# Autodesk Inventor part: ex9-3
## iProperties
Author: Administrator
Created: 2001-09
Part Number: ex9-3
Document SubType Name: Sheet Metal
Designer: Administrator
Control State: 0
Master: False
Checked Out: False
PropertySet Name: Design Tracking Control
Length Units: 11272
Angle Units: 11279
Time Units: 11290
Mass Units: 11286
Shininess: 3
Angle Display Precision: 2
Document Length Units: 11272
Document Angle Units: 11286
Document Time Units: 11279
Document Mass Units: 11290
Document Length Units Precision: 3
Document Angle Units Precision: 2
Compacted: False
PropertySet Name: _Private Model Information
Density: 0.0
Volumn: 0.0
Area: 0.0
PropertySet Name: Model Information
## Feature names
1. Plate1
2. Bend1
3. Plate2
4. Bend2
5. Cut1
